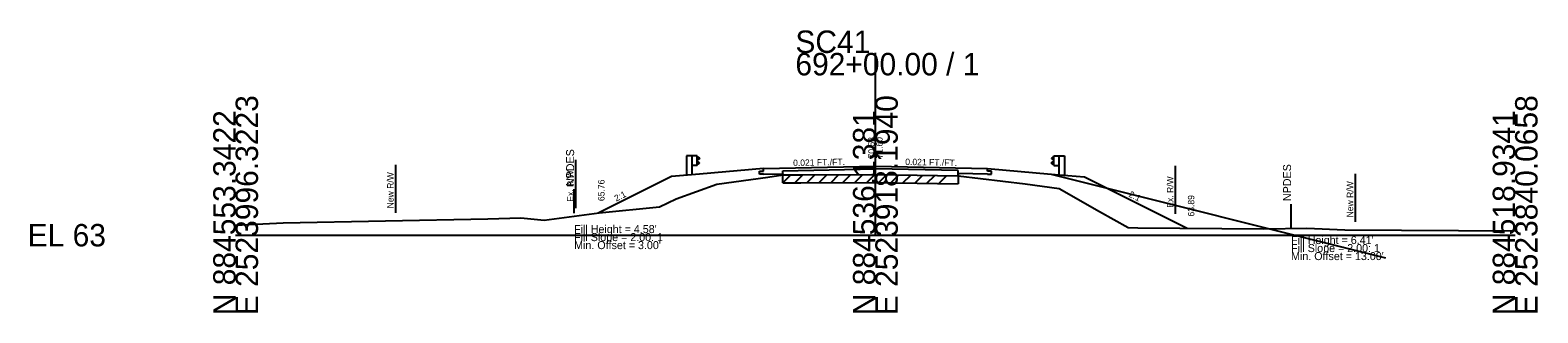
# Model space of a CAD drawing. Extents: x -26 to 183, y -10 to 24021.
# Drawn here: x -25.7 to 162.8, y 17990.3 to 18025.6 of the extents above; entities that cross this region are included whole.
import ezdxf

# ---------------------------------------------------------------- set-up
doc = ezdxf.new("R2010")
doc.units = 0
for name, color, linetype in [('RD_GPK_XS_Cell', 7, 'Continuous'), ('RD_XS_Base', 7, 'Continuous'), ('RD_XS_Buildup', 7, 'Continuous'), ('RD_XS_EarthShd', 7, 'Continuous'), ('RD_XS_ExGround', 7, 'Continuous'), ('RD_XS_ExPaveRet', 7, 'Continuous'), ('RD_XS_ExRW', 7, 'Continuous'), ('RD_XS_GR', 7, 'Continuous'), ('RD_XS_NewRW', 7, 'Continuous'), ('RD_XS_NPDES', 7, 'Continuous'), ('RD_XS_Pave', 7, 'Continuous'), ('RD_XS_TieSlope', 7, 'Continuous'), ('RD_XS_TX_Elev_EX', 7, 'Continuous'), ('RD_XS_TX_Elev_PR', 7, 'Continuous'), ('RD_XS_TX_Slope', 7, 'Continuous'), ('RD_XS_TX_Warning', 7, 'Continuous')]:
    doc.layers.add(name, color=color, linetype=linetype)

msp = doc.modelspace()

# ---------------------------------------------------------------- linework, layer by layer
at = {"layer": 'RD_GPK_XS_Cell'}
for p, q in [((80, 18000), (80, 18022.76)), ((0, 18000), (80, 18000)), ((80, 18000), (160, 18000))]:
    msp.add_line(p, q, dxfattribs=at)
at = {"layer": 'RD_XS_Base'}
for p, q in [((66, 18007.63), (68.44, 18007.68)), ((68.44, 18007.68), (68.44, 18007.54)), ((90.35, 18007.7), (90.35, 18007.42)), ((94, 18007.63), (90.35, 18007.7))]:
    msp.add_line(p, q, dxfattribs=at)
at = {"layer": 'RD_XS_Buildup'}
for p, q in [((68.44, 18008.04), (80, 18008.28)), ((68.44, 18007.54), (68.44, 18008.04)), ((90.35, 18008.06), (80, 18008.28)), ((90.35, 18007.42), (90.35, 18008.06))]:
    msp.add_line(p, q, dxfattribs=at)
at = {"layer": 'RD_XS_EarthShd'}
for p, q in [((58, 18007.64), (54.5, 18007.35)), ((66, 18008.31), (58, 18007.64)), ((94, 18008.31), (102, 18007.64)), ((102, 18007.64), (106.17, 18007.29))]:
    msp.add_line(p, q, dxfattribs=at)
at = {"layer": 'RD_XS_ExGround'}
for p, q in [((60.19, 18006.36), (66.56, 18007.26)), ((66.56, 18007.26), (68.44, 18007.54)), ((68.44, 18007.54), (70.66, 18007.53)), ((70.66, 18007.53), (79.56, 18007.59)), ((79.56, 18007.59), (80, 18007.58)), ((80, 18007.58), (82.65, 18007.54)), ((82.65, 18007.54), (90.35, 18007.42)), ((90.35, 18007.42), (98.71, 18006.4)), ((55.1, 18004.52), (60.19, 18006.36)), ((98.71, 18006.4), (103, 18005.83)), ((103, 18005.83), (108.01, 18002.96)), ((45.48, 18002.78), (52.99, 18003.54)), ((52.99, 18003.54), (55.1, 18004.52)), ((0, 18001.27), (5.93, 18001.53)), ((5.93, 18001.53), (31.53, 18002.03)), ((31.53, 18002.03), (35.66, 18002.16)), ((35.66, 18002.16), (38.59, 18001.88)), ((38.59, 18001.88), (45.48, 18002.78)), ((108.01, 18002.96), (111.62, 18000.94)), ((111.62, 18000.94), (112.84, 18000.93)), ((112.84, 18000.93), (128.58, 18000.81)), ((128.58, 18000.81), (133.96, 18000.86)), ((133.96, 18000.86), (138.7, 18000.68)), ((138.7, 18000.68), (160, 18000.53))]:
    msp.add_line(p, q, dxfattribs=at)
at = {"layer": 'RD_XS_ExPaveRet'}
for p, q in [((68.44, 18006.54), (69.43, 18007.54)), ((68.44, 18006.54), (68.44, 18007.54)), ((69.94, 18006.53), (70.94, 18007.53)), ((71.44, 18006.54), (72.44, 18007.54)), ((72.94, 18006.54), (73.94, 18007.55)), ((74.44, 18006.55), (75.44, 18007.56)), ((75.94, 18006.56), (76.94, 18007.57)), ((77.44, 18006.57), (78.44, 18007.58)), ((78.94, 18006.58), (79.94, 18007.58)), ((80.44, 18006.57), (81.42, 18007.56)), ((81.94, 18006.55), (82.92, 18007.54)), ((83.44, 18006.53), (84.42, 18007.51)), ((84.94, 18006.51), (85.92, 18007.49)), ((86.44, 18006.48), (87.42, 18007.47)), ((87.94, 18006.46), (88.92, 18007.44)), ((90.35, 18007.42), (90.35, 18006.42)), ((68.44, 18006.54), (70.66, 18006.53)), ((70.66, 18006.53), (79.56, 18006.59)), ((79.56, 18006.59), (80, 18006.58)), ((80, 18006.58), (82.65, 18006.54)), ((82.65, 18006.54), (90.35, 18006.42))]:
    msp.add_line(p, q, dxfattribs=at)
at = {"layer": 'RD_XS_ExRW'}
for p, q in [((42.5, 18009.39), (42.5, 18003.39)), ((117.5, 18008.65), (117.5, 18002.65))]:
    msp.add_line(p, q, dxfattribs=at)
at = {"layer": 'RD_XS_GR'}
for p, q in [((56.4, 18009.89), (56.4, 18007.51)), ((57.06, 18009.89), (56.4, 18009.89)), ((57.06, 18009.89), (57.06, 18007.56)), ((57.73, 18009.89), (57.06, 18009.89)), ((57.73, 18008.72), (57.06, 18008.72)), ((57.73, 18008.72), (57.73, 18009.89)), ((57.73, 18009.82), (58, 18009.62)), ((58, 18009.57), (57.73, 18009.37)), ((58, 18009.05), (57.73, 18009.25)), ((57.73, 18008.8), (58, 18009)), ((58, 18009.62), (58, 18009.57)), ((58, 18009), (58, 18009.05)), ((102.3, 18009.81), (102.02, 18009.61)), ((102.02, 18009.61), (102.02, 18009.56)), ((102.02, 18009.56), (102.3, 18009.36)), ((102.02, 18009.04), (102.3, 18009.24)), ((102.02, 18008.99), (102.02, 18009.04)), ((102.3, 18008.79), (102.02, 18008.99)), ((102.3, 18009.89), (102.96, 18009.89)), ((102.3, 18008.72), (102.3, 18009.89)), ((102.3, 18008.72), (102.96, 18008.72)), ((102.96, 18009.89), (102.96, 18007.56)), ((102.96, 18009.89), (103.63, 18009.89)), ((103.63, 18009.89), (103.63, 18007.5)), ((102.96, 18007.56), (102.96, 18007.56))]:
    msp.add_line(p, q, dxfattribs=at)
at = {"layer": 'RD_XS_NewRW'}
for p, q in [((20, 18008.8), (20, 18002.8)), ((140, 18007.67), (140, 18001.67))]:
    msp.add_line(p, q, dxfattribs=at)
at = {"layer": 'RD_XS_NPDES'}
for p, q in [((42.33, 18002.76), (42.33, 18005.76)), ((131.98, 18000.89), (131.98, 18003.89))]:
    msp.add_line(p, q, dxfattribs=at)
at = {"layer": 'RD_XS_Pave'}
for p, q in [((65.5, 18007.98), (66, 18007.99)), ((65.5, 18007.62), (65.5, 18007.98)), ((66, 18007.63), (65.5, 18007.62)), ((66, 18008.31), (80, 18008.6)), ((66, 18007.99), (66, 18008.31)), ((80, 18008.6), (94, 18008.31)), ((94, 18007.99), (94, 18008.31)), ((94.5, 18007.98), (94, 18007.99)), ((94, 18007.63), (94.5, 18007.62)), ((94.5, 18007.62), (94.5, 18007.98)), ((102, 18007.64), (143.79, 17997.19))]:
    msp.add_line(p, q, dxfattribs=at)
at = {"layer": 'RD_XS_TieSlope'}
for p, q in [((54.5, 18007.35), (45.33, 18002.76)), ((106.17, 18007.29), (118.98, 18000.89))]:
    msp.add_line(p, q, dxfattribs=at)

# ---------------------------------------------------------------- texts
at = {"layer": 'RD_GPK_XS_Cell'}
for s, p in [('SC41', (70, 18022.76)), ('692+00.00 / 1', (70, 18019.96)), ('EL 63', (-26, 17998.6))]:
    msp.add_text(s, height=2.8, dxfattribs=at).set_placement(p)
for s, p in [('E 2523996.3223', (2.8, 17990)), ('E 2523918.1940', (82.8, 17990)), ('E 2523840.0658', (162.8, 17990)), ('N 884553.3422', (0, 17990)), ('N 884536.1381', (80, 17990)), ('N 884518.9341', (160, 17990))]:
    msp.add_text(s, height=2.8, rotation=90, dxfattribs=at).set_placement(p)
at = {"layer": 'RD_XS_ExRW'}
for p in [(42.25, 18004.18), (117.25, 18003.43)]:
    msp.add_text('Ex. R/W ', height=0.8, rotation=90, dxfattribs=at).set_placement(p)
at = {"layer": 'RD_XS_NewRW'}
for p in [(19.75, 18003.35), (139.75, 18002.22)]:
    msp.add_text('New R/W ', height=0.8, rotation=90, dxfattribs=at).set_placement(p)
at = {"layer": 'RD_XS_TX_Elev_EX'}
msp.add_text('70.58', height=0.8, rotation=90, dxfattribs=at).set_placement((79.9, 18009.58))
at = {"layer": 'RD_XS_TX_Elev_PR'}
for s, p in [('71.60', (80.9, 18009.58)), ('65.76', (46.13, 18004.26)), ('63.89', (119.88, 18002.33))]:
    msp.add_text(s, height=0.8, rotation=90, dxfattribs=at).set_placement(p)
at = {"layer": 'RD_XS_TX_Slope'}
for s, rotation, p in [('0.021 FT./FT.', 1.1916, (69.72, 18008.63)), ('0.021 FT./FT.', 358.8084, (83.73, 18008.77)), ('2:1', 26.5651, (47.6, 18004.18)), ('2:1', 333.4349, (111.6, 18004.84))]:
    msp.add_text(s, height=0.8, rotation=rotation, dxfattribs=at).set_placement(p)
at = {"layer": 'RD_XS_TX_Warning'}
for p in [(42.33, 18005.76), (131.98, 18003.89)]:
    msp.add_text(' NPDES', height=1, rotation=90, dxfattribs=at).set_placement(p)
for s, p in [("Fill Height = 4.58' ", (42.33, 18000.26)), ('Fill Slope = 2.00: 1', (42.33, 17999.26)), ("Min. Offset = 3.00' ", (42.33, 17998.26)), ("Fill Height = 6.41' ", (131.98, 17998.89)), ('Fill Slope = 2.00: 1', (131.98, 17997.89)), ("Min. Offset = 13.00' ", (131.98, 17996.89))]:
    msp.add_text(s, height=1, dxfattribs=at).set_placement(p)

doc.saveas('drawing.dxf')
